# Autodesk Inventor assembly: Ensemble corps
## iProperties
Shininess: 41.0
Length Units: 11269
Angle Units: 11279
Time Units: 11290
Mass Units: 11283
Length Display Precision: 3
Angle Display Precision: 2
Created: 2002-11
Part Number: Ensemble corps
Document SubType Name: Assemblage
Designer: poste-2
Density: 0.0
Volumn: 0.0
Area: 0.0
PropertySet Name: Model Information
Control State: 0
Master: False
Checked Out: False
Author: poste-2
